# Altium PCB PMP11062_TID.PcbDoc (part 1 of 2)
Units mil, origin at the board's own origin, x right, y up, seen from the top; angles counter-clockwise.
Board outline 8000 x 4750 mil, 2 copper layers (Top Layer, Bottom Layer), stack 62 mil thick; 95 components, 41 nets, 236 pads, 20 vias.
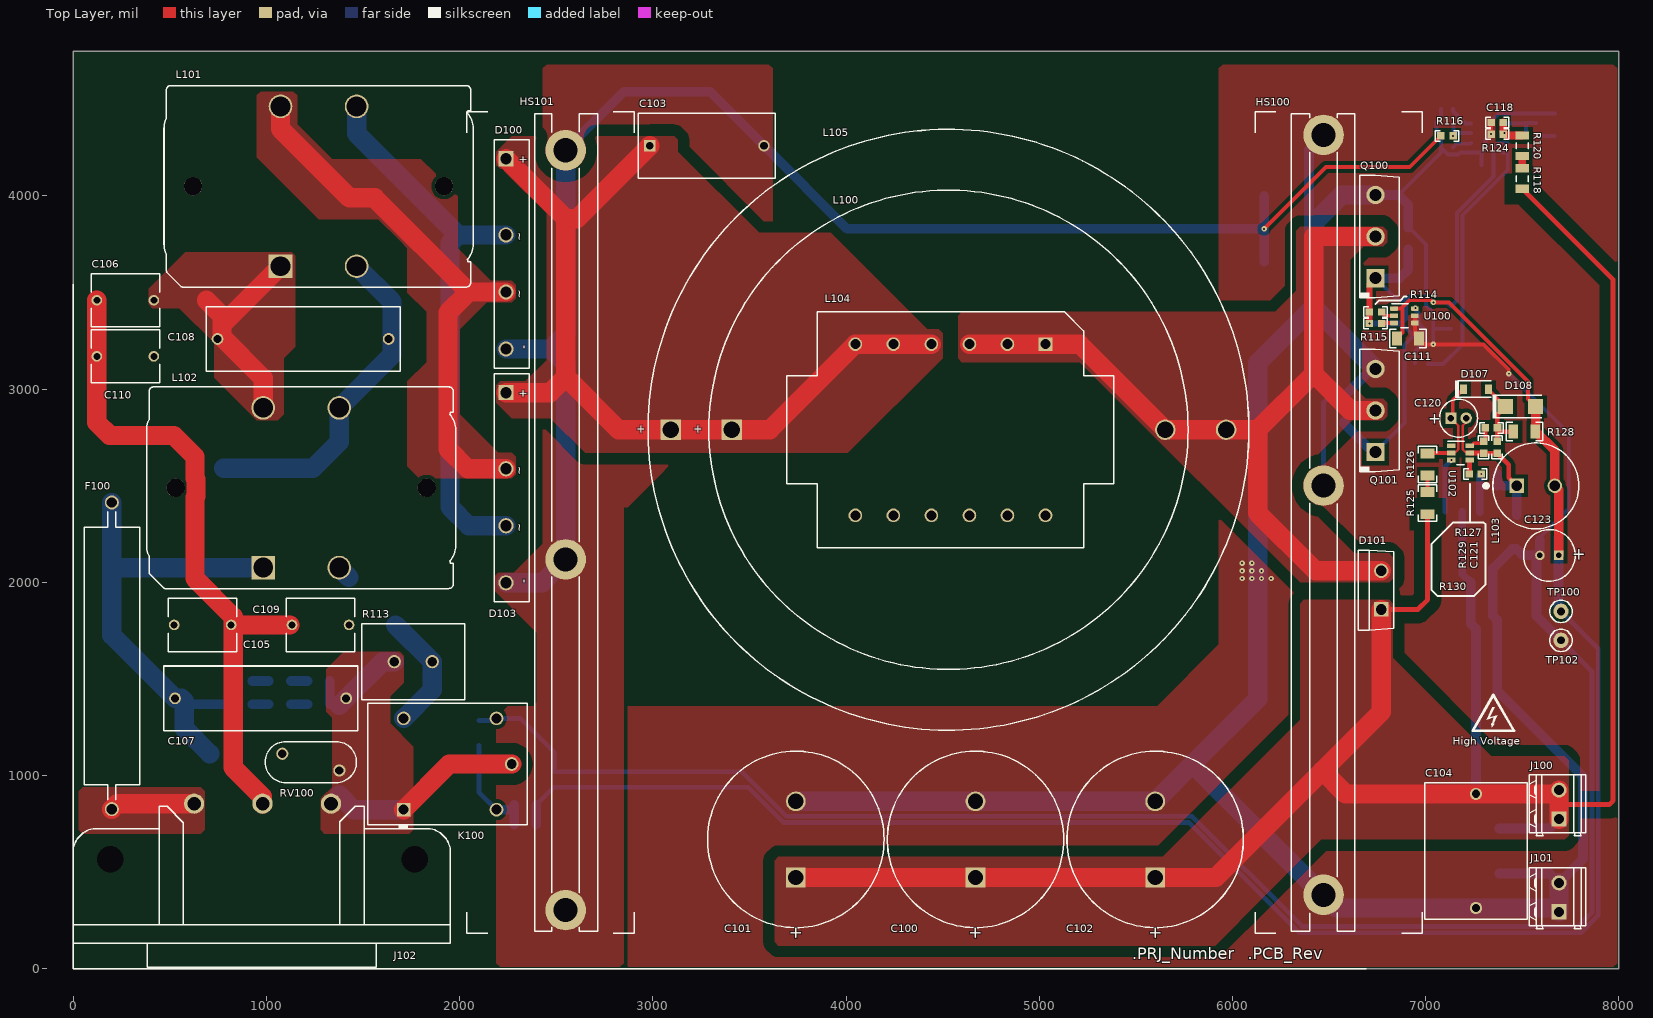
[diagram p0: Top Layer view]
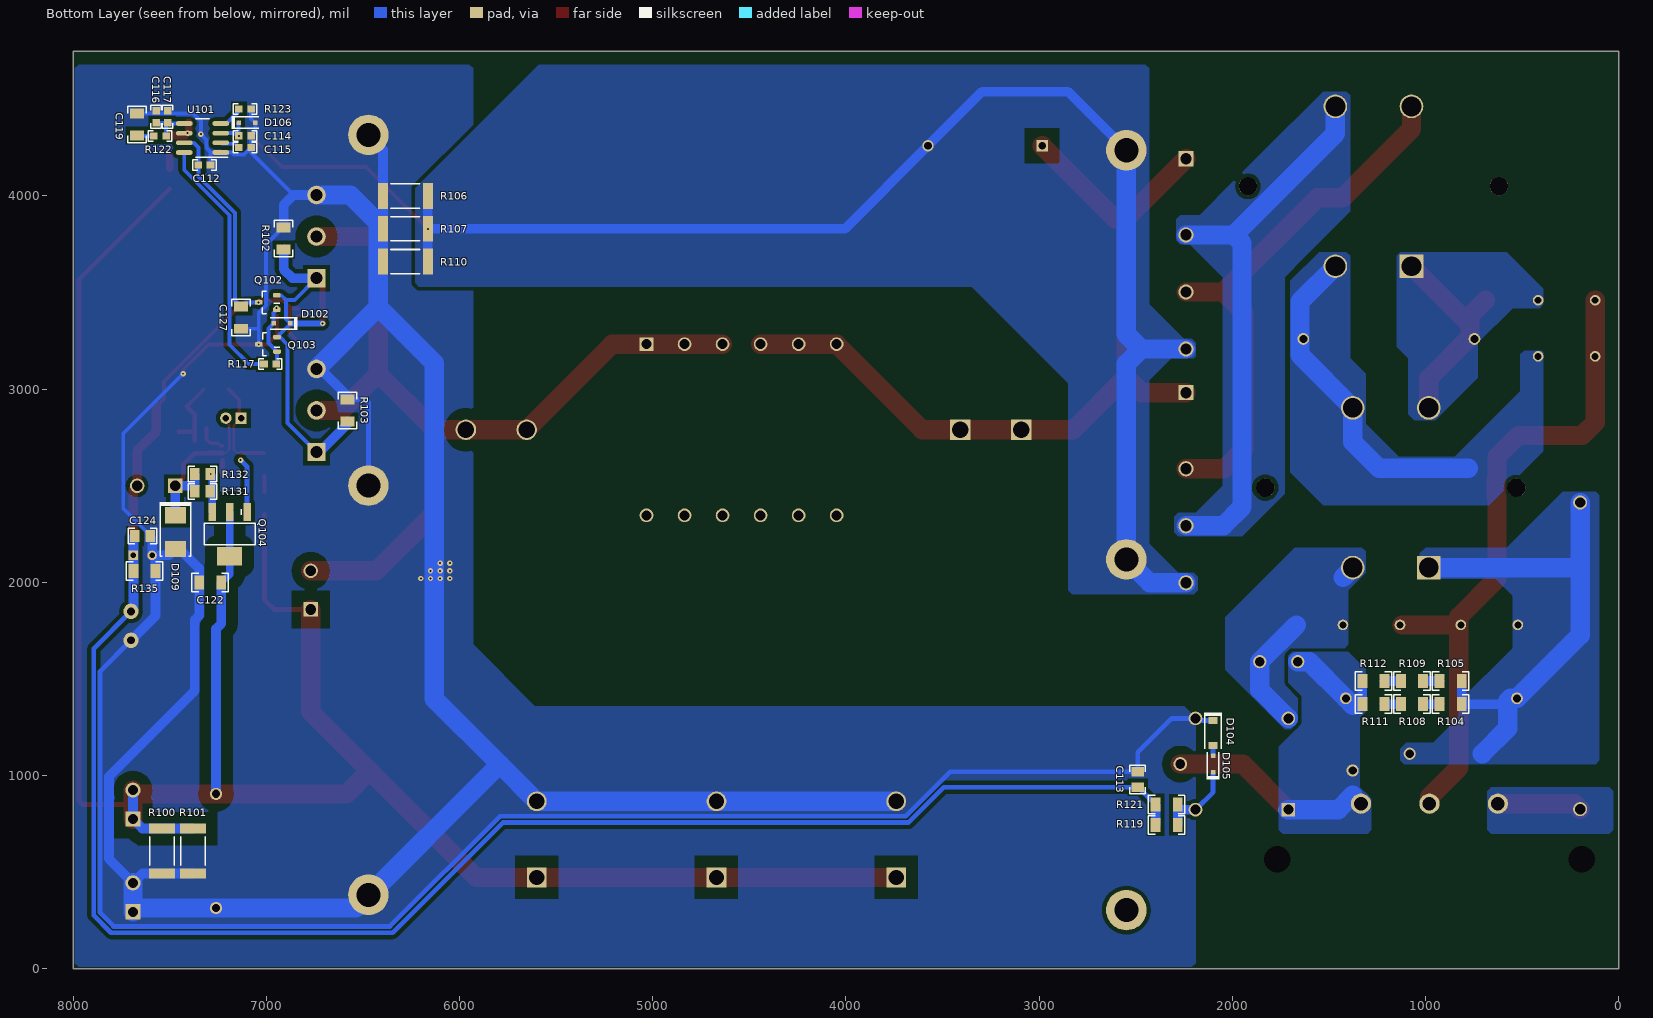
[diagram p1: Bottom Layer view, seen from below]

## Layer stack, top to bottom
Top Solder: solder mask 0.4, Solder Resist, Dk 3.5
Top Layer: signal copper 1.4
Dielectric1: core 59.2, FR-4, Dk 4.8
Bottom Layer: signal copper 1.4
Bottom Solder: solder mask 0.4, Solder Resist, Dk 3.5

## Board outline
0,0 8000,0 8000,4750 0,4750

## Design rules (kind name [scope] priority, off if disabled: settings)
AcuteAngle [All] p1: minimum=4.50000000000000E+0001 checktracksonly=FALSE
AssemblyTestPointUsage [All] p1: valid=2
Clearance Clearance_1 [InNetClass('HV') vs (InNet('GND') OR InNet('NetC103_2'))] p1: gap=60
Clearance Clearance_Keepouts [((IsTrack Or IsArc) And Not InPoly) And IsFree and IsKeepOut vs ((IsTrack Or IsArc) And Not InPoly) And IsFree and IsKeepOut] p2: gap=0
Clearance Clearance_BoardEdge_MountingHoles [OnCopper and InComponentClass('Mounting Holes') vs IsKeepOut] p3: gap=40
Clearance Clearance_BoardEdge_Poly [OnCopper and InPoly vs IsKeepOut] p4: gap=25
Clearance Clearance_BoardEdge [OnCopper and Not InComponentClass('Logo') and not InComponentClass('FiducialMark') and not InRegion(1000,500,4000,800) and Not IsKeepout vs IsKeepOut] p5: gap=75
Clearance Clearance_Poly [InPolygon] p6: gap=20
Clearance [All] p7: gap=7.87
ComponentClearance ComponentClearance_MountingHoles_FiducialMarks [InComponentClass('Mounting Holes') vs InComponentClass('FiducialMark')] p1: gap=20 collisioncheckmode=3 verticalgap=10 showdistances=FALSE
ComponentClearance ComponentClearance_Shunt [InComponentClass('Header') vs InComponentClass('Shunt')] p2: gap=0 collisioncheckmode=3 verticalgap=0 showdistances=FALSE
ComponentClearance ComponentClearance_Logo [InComponentClass('Logo')] p3: gap=5 collisioncheckmode=3 verticalgap=10 showdistances=FALSE
ComponentClearance ComponentClearance_ScrewToNut [(HasFootprint('NY PMS 440 0025 PH')) vs (HasFootprint('Keystone_1902C'))] p4: gap=20 collisioncheckmode=3 verticalgap=100000 showdistances=FALSE
ComponentClearance ComponentClearance_MountingHoles [InComponentClass('Mounting Holes')] p5: gap=20 collisioncheckmode=3 verticalgap=10 showdistances=FALSE
ComponentClearance ComponentClearance_SmallPassives [HasFootprint('0201*') or HasFootprint('0402*') or HasFootprint('0508') or HasFootprint('0603*') or HasFootprint('0612') or HasFootprint('0805*') or HasFootprint('0815*') or HasFootprint('0830*') or HasFootprint('1206*') or HasFootprint('1210*') or HasFootprint('1808*') or HasFootprint('1812*') or HasFootprint('1825*') or HasFootprint('2010*') or HasFootprint('2220*') or HasFootprint('2225*') or HasFootprint('2512*') or HasFootprint('2728*') or HasFootprint('3518*') vs HasFootprint('0201*') or HasFootprint('0402*') or HasFootprint('0508') or HasFootprint('0603*') or HasFootprint('0612') or HasFootprint('0805*') or HasFootprint('0815*') or HasFootprint('0830*') or HasFootprint('1206*') or HasFootprint('1210*') or HasFootprint('1808*') or HasFootprint('1812*') or HasFootprint('1825*') or HasFootprint('2010*') or HasFootprint('2220*') or HasFootprint('2225*') or HasFootprint('2512*') or HasFootprint('2728*') or HasFootprint('3518*')] p6: gap=20 collisioncheckmode=3 verticalgap=20 showdistances=FALSE
ComponentClearance ComponentClearance_THtoSMT [IsThruComponent vs IsSMTComponent] p7: gap=10 collisioncheckmode=3 verticalgap=10 showdistances=FALSE
ComponentClearance ComponentClearance_THtoTH [IsThruComponent vs IsThruComponent] p8: gap=10 collisioncheckmode=3 verticalgap=10 showdistances=FALSE
ComponentClearance [All] p9: gap=10 collisioncheckmode=3 verticalgap=10 showdistances=FALSE
DiffPairsRouting [All] p1: maxlimit=100 minlimit=10 mostfreqgap=10 toplayer_minwidth=15 toplayer_maxwidth=15 toplayer_prefwidth=15 bottomlayer_minwidth=15 bottomlayer_maxwidth=15 bottomlayer_prefwidth=15 maxuncoupledlength=1000
FabricationTestPointUsage TestPointUsage [All] p1: valid=2 allowmultiple=FALSE
FabricationTestpoint Testpoint [All] p1: side=3 testpointundercomponent=TRUE minsize=40 maxsize=100 preferedsize=60 minholesize=0 maxholesize=40 preferedholesize=32 testpointgrid=1 allowsidetop=TRUE allowsidebottom=TRUE usegrid=TRUE gridtolerance=0.01
FanoutControl Fanout_LCC [IsLCC] p1: bgadir=Out bgaviamode=Centered fanoutstyle=Auto fanoutdirection=Alternating viagrid=1 // Fanout_LCC (Default Rule)
FanoutControl Fanout_BGA [IsBGA] p2: bgadir=Out bgaviamode=Centered fanoutstyle=Auto fanoutdirection=Alternating viagrid=1 // Fanout_BGA (Default Rule)
FanoutControl Fanout_Default [All] p4: bgadir=Out bgaviamode=Centered fanoutstyle=Auto fanoutdirection=Alternating viagrid=1 // Fanout_Default (Default Rule)
FanoutControl Fanout_Small [(CompPinCount < 5)] p5: bgadir=Out bgaviamode=Centered fanoutstyle=Auto fanoutdirection=OutThenIn viagrid=1 // Fanout_Small (Default Rule)
Height [All] p1: minheight=0 maxheight=3000 prefheight=500
HoleSize [All] p1: absolutevalues=TRUE maxlimit=251 minlimit=7 maxpercent=80.000 minpercent=20.000
MinimumAnnularRing MinimumAnnularRing_ThermalPadVias [IsVia and InAnyComponent] p1: minimumring=5.91
MinimumAnnularRing [All] p2: minimumring=9
MinimumSolderMaskSliver MinimumSolderMaskSliver_Logo [InComponentClass('Logo') vs InComponentClass('Logo')] p1: minsoldermaskwidth=0.7
MinimumSolderMaskSliver [All] p2: minsoldermaskwidth=2
PlaneConnect [All] p1: planeconnectstyle=Relief reliefexpansion=10 reliefentries=4 reliefconductorwidth=10 reliefairgap=10
PolygonConnect PolygonConnect_7 [All vs IsNamedPolygon('F100_1') Or  IsNamedPolygon('C103_1') Or  IsNamedPolygon('C106_1') Or  IsNamedPolygon('D100_2') Or  IsNamedPolygon('C106_1') Or  IsNamedPolygon('C105_1') Or  IsNamedPolygon('C109_2') Or  IsNamedPolygon('B+') Or  IsNamedPolygon('C107_2') Or  IsNamedPolygon('C108_2') Or  IsNamedPolygon('F100_1') Or  IsNamedPolygon('C103_2') Or  IsNamedPolygon('C107_2') Or  IsNamedPolygon('D100_3') Or  IsNamedPolygon('D101_2')] p1: connectstyle=Direct reliefconductorwidth=10 reliefentries=4 polygonreliefangle="90 Angle" airgapwidth=10
PolygonConnect PolygonConnect_6 [All vs IsNamedPolygon('GND2') Or  IsNamedPolygon('SGND') Or  IsNamedPolygon('GND1') Or  IsNamedPolygon('C901_1') Or  IsNamedPolygon('SGND') Or  IsNamedPolygon('GND2') Or  IsNamedPolygon('GND1')] p2: connectstyle=Direct reliefconductorwidth=10 reliefentries=4 polygonreliefangle="90 Angle" airgapwidth=10
PolygonConnect PolygonConnect_5 [All vs IsNamedPolygon('GND1') Or  IsNamedPolygon('GND1')] p3: connectstyle=Direct reliefconductorwidth=10 reliefentries=4 polygonreliefangle="90 Angle" airgapwidth=10
PolygonConnect PolygonConnect_4 [All vs IsNamedPolygon('C21_1') Or  IsNamedPolygon('C5_1') Or  IsNamedPolygon('C12_2') Or  IsNamedPolygon('C2_2') Or  IsNamedPolygon('C13_1') Or  IsNamedPolygon('C28_1') Or  IsNamedPolygon('C6_1') Or  IsNamedPolygon('GND') Or  IsNamedPolygon('GND2') Or  IsNamedPolygon('C14_1') Or  IsNamedPolygon('C13_1') Or  IsNamedPolygon('Q1_3') Or  IsNamedPolygon('C14_1') Or  IsNamedPolygon('C5_1') Or  IsNamedPolygon('GND2') Or  IsNamedPolygon('C28_1') Or  IsNamedPolygon('D5_2') Or  IsNamedPolygon('D6_2') Or  IsNamedPolygon('D2_1') Or  IsNamedPolygon('C12_2') Or  IsNamedPolygon('D2_1') Or  IsNamedPolygon('C4_1') Or  IsNamedPolygon('C4_1') Or  IsNamedPolygon('C2_2') Or  IsNamedPolygon('GND') Or  IsNamedPolygon('C33_1') Or  IsNamedPolygon('C9_1')] p4: connectstyle=Direct reliefconductorwidth=10 reliefentries=4 polygonreliefangle="90 Angle" airgapwidth=10
PolygonConnect PolygonConnect_3 [All vs IsNamedPolygon('C28_1') Or  IsNamedPolygon('C12_2') Or  IsNamedPolygon('C28_1') Or  IsNamedPolygon('C9_1') Or  IsNamedPolygon('D5_2') Or  IsNamedPolygon('C12_2') Or  IsNamedPolygon('C2_2') Or  IsNamedPolygon('C14_1') Or  IsNamedPolygon('C4_1') Or  IsNamedPolygon('C14_1') Or  IsNamedPolygon('D6_2') Or  IsNamedPolygon('GND2') Or  IsNamedPolygon('Q1_3') Or  IsNamedPolygon('C5_1') Or  IsNamedPolygon('D2_1') Or  IsNamedPolygon('C4_1') Or  IsNamedPolygon('C13_1') Or  IsNamedPolygon('C5_1') Or  IsNamedPolygon('C13_1') Or  IsNamedPolygon('C33_1') Or  IsNamedPolygon('D2_1') Or  IsNamedPolygon('GND') Or  IsNamedPolygon('GND') Or  IsNamedPolygon('GND2') Or  IsNamedPolygon('C2_2') Or  IsNamedPolygon('C6_1') Or  IsNamedPolygon('C21_1')] p5: connectstyle=Direct reliefconductorwidth=10 reliefentries=4 polygonreliefangle="90 Angle" airgapwidth=10
PolygonConnect PolygonConnect_2 [All vs IsNamedPolygon('C21_1') Or  IsNamedPolygon('C4_1') Or  IsNamedPolygon('D5_2') Or  IsNamedPolygon('C5_1') Or  IsNamedPolygon('C14_1') Or  IsNamedPolygon('C13_1') Or  IsNamedPolygon('C4_1') Or  IsNamedPolygon('C33_1') Or  IsNamedPolygon('C12_2') Or  IsNamedPolygon('D2_1') Or  IsNamedPolygon('C2_2') Or  IsNamedPolygon('C28_1') Or  IsNamedPolygon('C12_2') Or  IsNamedPolygon('D2_1') Or  IsNamedPolygon('C5_1') Or  IsNamedPolygon('Q1_3') Or  IsNamedPolygon('GND') Or  IsNamedPolygon('D6_2') Or  IsNamedPolygon('C6_1') Or  IsNamedPolygon('C2_2') Or  IsNamedPolygon('C14_1') Or  IsNamedPolygon('C28_1') Or  IsNamedPolygon('C13_1') Or  IsNamedPolygon('C9_1') Or  IsNamedPolygon('GND')] p6: connectstyle=Direct reliefconductorwidth=10 reliefentries=4 polygonreliefangle="90 Angle" airgapwidth=10
PolygonConnect PolygonConnect_1 [All vs IsNamedPolygon('C28_1') Or  IsNamedPolygon('D5_2') Or  IsNamedPolygon('C5_1') Or  IsNamedPolygon('C5_1') Or  IsNamedPolygon('D2_1') Or  IsNamedPolygon('C21_1') Or  IsNamedPolygon('C9_1') Or  IsNamedPolygon('C4_1') Or  IsNamedPolygon('C14_1') Or  IsNamedPolygon('C28_1') Or  IsNamedPolygon('C6_1') Or  IsNamedPolygon('C12_2') Or  IsNamedPolygon('C33_1') Or  IsNamedPolygon('C4_1') Or  IsNamedPolygon('C13_1') Or  IsNamedPolygon('C12_2') Or  IsNamedPolygon('D6_2') Or  IsNamedPolygon('C2_2') Or  IsNamedPolygon('C14_1') Or  IsNamedPolygon('D2_1') Or  IsNamedPolygon('C2_2') Or  IsNamedPolygon('C13_1')] p7: connectstyle=Direct reliefconductorwidth=10 reliefentries=4 polygonreliefangle="90 Angle" airgapwidth=10
PolygonConnect [All] p8: connectstyle=Relief reliefconductorwidth=10 reliefentries=4 polygonreliefangle="90 Angle" airgapwidth=10
RoutingVias ThermalPadVias [IsVia and InAnyComponent] p1: holewidth=7.87 width=19.68 viastyle="Through Hole" minholewidth=7.87 minwidth=19.68 maxholewidth=12.99 maxwidth=23.62
RoutingVias [All] p2: holewidth=16 width=34 viastyle="Through Hole" minholewidth=7.87 minwidth=26 maxholewidth=40 maxwidth=65
SilkToBoardRegionClearance [Not ((IsComment or IsDesignator) And (Hide <> 'False')) and not InRegion(1000,500,4000,800)] p1:
SilkToSilkClearance SilkToSilkClearance_Pb-FreeLogo [(HasFootprint('Pb-Free_Overlay_Medium') OR HasFootprint('Pb-Free_Overlay_Small')) vs (HasFootprint('Pb-Free_Overlay_Medium') OR HasFootprint('Pb-Free_Overlay_Small'))] p1: silktosilkclearance=0
SilkToSilkClearance [All] p2: silktosilkclearance=1
SilkToSolderMaskClearance "Silk to Solder Mask Opening" [All] p1: minsilkscreentomaskgap=1 clearancetoexposedcopper=FALSE
SolderMaskExpansion [All] p1: expansion=1.97
UnpouredPolygon [All] p1: allowunpoured=FALSE
Width [All] p1: maxlimit=100 minlimit=6 preferedwidth=10 checkconnectedcopper=TRUE
13 further rules are at their usual default settings.

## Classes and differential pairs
net class HV: B+ NetC103_1 NetC105_1 NetC106_1 NetC107_2 NetC109_2 NetD101_2 NetF100_1

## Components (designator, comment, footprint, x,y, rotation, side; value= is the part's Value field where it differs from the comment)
C100 "450HXG180MEFCSN22X45" SMQ_2200X2500 4670,670 r90 top
C101 "450HXG180MEFCSN22X45" SMQ_2200X2500 3740,670 r90 top
C102 "450HXG180MEFCSN22X45" SMQ_2200X2500 5600,670 r90 top
C103 "B32922C3334M" B32922_14.5mm 3280,4260 r0 top
C104 "450MPK105J" MPK_1800x2000x1350 7260,610 r270 top
C105 "DE6E3KJ222MN3A" E_900x700x900 670,1780 r0 top
C106 "DE6E3KJ222MN3A" E_900x700x900 270,3460 r180 top
C107 "ECQ-U2A474ML" CAPRR2250W80L2550T850H1750 970,1400 r0 top
C108 "ECQ-U2A474ML" CAPRR2250W80L2550T850H1750 1190,3260 r0 top
C109 "DE6E3KJ222MN3A" E_900x700x900 1280,1780 r0 top
C110 "DE6E3KJ222MN3A" E_900x700x900 270,3170 r0 top
C111 "C3216X7R1H105K160AB" 1206 6907.68,3262.49 r0 top
C112 "C0603C474K8RACTU" 0603 7320,4160 r180 bottom
C113 "0805YD105KAT2A" 0805_HV 2490,980 r270 bottom
C114 "06031C471JAT2A" 0603 7110,4311.46 r180 bottom
C115 "C0603C102J5RACTU" 0603 7110,4251.46 r180 bottom
C116 "C0603C105K4PACTU" 0603 7570,4410 r90 bottom
C117 "C0603C474K8RACTU" 0603 7510,4410 r90 bottom
C118 "CL10C102JB8NNNC" 0603 7370,4380 r180 top
C119 "GRM31MR61A106KE19L" 1206 7670,4370 r90 bottom
C120 "UVR1V100MDD1TA" CAPPR2-5x11 7170,2850 r0 top
C121 "06035A220JAT2A" 0603 7370,2700 r270 top
C122 "GRM31BR72J682KW01L" 1206 7290,2000 r0 bottom
C123 "EEU-FR1E151B" CAPPR250W50D630H1120 7640,2140 r180 top
C124 "08055C105KAT2A" 0805_HV 7640,2240 r180 bottom
C127 "C3216X7R1H105K160AB" 1206 7130,3370 r270 bottom
D100 "D25XB60-7000" 5S 2240,3700 r270 top
D101 "CVFD20065A" TO-220-2 6770,1960 r90 top
D102 "BAT54HT1G" sod-323 6918.7,3340.16 r0 bottom
D103 "D25XB60-7000" 5S 2240,2490 r270 top
D104 "MMSZ4699T1G" SOD-123 2100,1220 r270 bottom
D105 "BAS316,115" sod-323 2100,1060 r90 bottom
D106 "BAT54HT1G" sod-323 7100,4380 r180 bottom
D107 "1N4148W-7-F" SOD-123 7260,3000 r0 top
D108 "ES1J-TP" SMA 7490,2910 r0 top
D109 "MURS160-13-F" SMB 7470,2260 r270 bottom
F100 "0325020.MXP" FUSE_0325 200,1620 r90 top
"High Voltage" "DANGER HIGH VOLTAGE" IEC_HighVoltage_Small 7350,1320 r0 top
HS100 "782653B04250G" HEATSINK_782653B04250G 6550,2310 r270 top
HS101 "782653B04250G" HEATSINK_782653B04250G 2470,2310 r90 top
J100 "691214310002" Wurth_691214310002 7690,850 r90 top
J101 "691214310002" Wurth_691214310002 7690,370 r90 top
J102 "703W-00/54" CONN_QUALTEK-703W-0054 980,460 r180 top
K100 "875B-1CC-F-S-12VDC" RELAY_875 1990,1060 r90 top
L100 "G154015" G154015 4530,2790 r0 top
L101 "7448062105" WE-CMBNC_XXL 1270,4050 r90 top
L102 "7448062105" WE-CMBNC_XXL 1180,2490 r90 top
L103 "RFS1113-224ME" RFS1113 7570,2500 r0 top
L104 "G154021LF" G154021LF 4540,2790 r270 top
L105 "G154016" G154016 4530,2790 r0 top
Q100 "IPW60R099CP" TO-247 6740,3790 r90 top
Q101 "IPW60R099CP" TO-247 6740,2890 r90 top
Q102 "FMMT620TA" SOT-23 6992.13,3449.06 r0 bottom
Q103 "FMMT718TA" SOT-23 6991.66,3232.17 r0 bottom
Q104 "STN2580" SOT-223 7190,2250 r270 bottom
R100 "CRCW2512330KJNEG" 2512 7539.68,610 r90 bottom
R101 "CRCW2512330KJNEG" 2512 7380,610 r90 bottom
R102 "CRCW120620K0JNEA" 1206 6910,3780 r270 bottom
R103 "CRCW120620K0JNEA" 1206 6580,2890 r270 bottom
R104 "CRCW1206432KFKEA" 1206 870,1370 r180 bottom
R105 "CRCW1206432KFKEA" 1206 870,1490 r180 bottom
R106 "1-2176057-4" 2512 6280,4000 r0 bottom
R107 "1-2176057-4" 2512 6280,3830 r0 bottom
R108 "CRCW1206432KFKEA" 1206 1070,1370 r180 bottom
R109 "CRCW1206432KFKEA" 1206 1070,1490 r180 bottom
R110 "1-2176057-4" 2512 6280,3660 r0 bottom
R111 "CRCW1206432KFKEA" 1206 1270,1370 r180 bottom
R112 "CRCW1206432KFKEA" 1206 1270,1490 r180 bottom
R113 "TWW10J10RE" TWW10 1760,1590 r180 top
R114 "CRCW060310R0JNEAHP" 0603 6740,3400 r0 top
R115 "CRCW06031R00JNEA" 0603 6740,3340 r180 top
R116 "CRCW0603221RFKEA" 0603 7110,4311.46 r180 top
R117 "CRCW060310R0JNEAHP" 0603 6980,3130 r0 bottom
R118 "CRCW1206499KFKEA" 1206L 7500,4090 r270 top
R119 "CRCW1206150RJNEA" 1206 2340,745.04 r0 bottom
R120 "CRCW1206499KFKEA" 1206L 7500,4260 r270 top
R121 "CRCW1206150RJNEA" 1206 2340,850 r0 bottom
R122 "CRCW06035K90FKEA" 0603 7550,4310 r180 bottom
R123 "CRCW060310K5FKEA" 0603 7110,4450 r0 bottom
R124 "CRCW060313K3FKEA" 0603 7370,4320 r0 top
R125 "CRCW12063M30JNEA" 1206 7010,2410 r90 top
R126 "CRCW12063M30JNEA" 1206 7010,2610 r90 top
R127 "CRCW060349K9FKEA" 0603 7340,2800 r0 top
R128 "CRCW1206475KFKEA" 1206 7510,2780 r180 top
R129 "CRCW060317K8FKEA" 0603 7300,2700 r90 top
R130 "CRCW0603511RFKEA" 0603 7256,2561.46 r180 top
R131 "CRCW08051R20JNEA" 0805_HV 7330,2471.46 r0 bottom
R132 "CRCW08051R20JNEA" 0805_HV 7330,2561.46 r0 bottom
R135 "CRCW120612K0JNEA" 1206 7630,2060 r0 bottom
RV100 "S10K275E2" VAR_S10K275E2 1230,1070 r180 top
TP100 "5000" Keystone5000 7700,1850 r90 top
TP102 "5001" Keystone5001 7700,1700 r90 top
U100 "UCC27511DBVR" DBV0006A_N#1 6890,3380 r0 top
U101 "UCC28180D" D0008A_N 7330,4300 r0 bottom
U102 "UCC28722DBV" DBV0006A_N#2 7180,2670 r0 top

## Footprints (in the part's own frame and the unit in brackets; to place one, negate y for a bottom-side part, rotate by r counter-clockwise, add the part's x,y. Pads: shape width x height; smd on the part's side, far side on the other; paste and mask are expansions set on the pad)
5S [mm] "TH, 4-Leads, Body 4.6x30mm"
  rect 2x2 hole 1.5: 1(-12.5,0)
  round 2 hole 1.5: 2(-2.5,0) 3(5,0) 4(12.5,0)
  silkscreen extent -15,-1.55 15,3.05, body extent -15,-1.55 15,3.05, height 24
0603 [mm] "0603 from SM-752 data"
  rect 1x0.95 smd: 1(-0.8,0) 2(0.8,0)
  silkscreen extent -1.52,-0.69 1.52,0.69, body extent -0.87,-0.47 0.87,0.47, height 1
0805_HV [mil] "0805 with 30mil clearance between pads"
  rect 50x63 smd: 1(-40,0) 2(40,0)
  silkscreen extent -74,-40 74,40, body extent -43,-29 43,29, height 43
1206 [mm] "1206 from SM-752 data"
  rect 1.3x1.85 smd: 1(-1.45,0) 2(1.45,0)
  silkscreen extent -2.4,-1.21 2.4,1.21, body extent -1.7,-0.9 1.7,0.9, height 1.35
1206L [mm] "1206 from SM-752 data"
  rect 1.1x1.75 smd: 1(-1.35,0) 2(1.35,0)
  silkscreen extent -0.4,-0.77 0.4,0.77, body extent -1.7,-0.9 1.7,0.9, height 1.35
2512 [mm] "Chip Resistor, Body 6.3x3.2mm, IPC Medium Density"
  rect 1.3x3.4 smd: 1(-2.95,0) 2(2.95,0)
  silkscreen extent -1.9,-1.6 1.9,1.6, body extent -3.22,-1.67 3.22,1.67, height 0.71
B32922_14.5mm [mm] "Epcos film capacitors, 15mm spacing"
  rect 1.5x1.5 hole 1: 1(-7.5,0)
  round 1.5 hole 1: 2(7.5,0)
  silkscreen extent -9,-4.25 9,4.25, body extent -9,-4.25 9,4.25, height 14.5
CAPPR2-5x11 [mm] "Capacitor, Electrolytic, Radial; Body 5 x 11 mm (Dia.xH typ); Pin Spacing 2 mm (typ)"
  rect 1.5x1.5 hole 0.85: 1(-1,0)
  round 1.5 hole 0.85: 2(1,0)
  silkscreen extent -2.5,-2.5 2.5,2.5, body extent -2.53,-2.53 2.53,2.52, height 11.29
CAPPR250W50D630H1120 [mm] "PANASONIC"
  rect 1.25x1.25 hole 0.75: 1(-1.25,0)
  round 1.25 hole 0.75: 2(1.25,0)
  silkscreen extent -3.4,-3.4 3.4,3.4, body extent -3.37,-3.39 3.4,3.39, height 12.21
CAPRR2250W80L2550T850H1750 [mm] "PANASONIC"
  round 1.55 hole 1.05: 1(-11.25,0) 2(11.25,0)
  silkscreen extent -12.75,-4.25 12.75,4.25, body extent -12.75,-4.25 12.75,4.25, height 17.5
CONN_QUALTEK-703W-0054 [mil] "AC Receptacle"
  round 105 hole 70: 1(354.33,-395) 2(-354.33,-395) 3(0,-395)
  round 39.37 hole 137.8 unplated: MH1(-787.4,-107.36) MH2(787.4,-107.36)
  silkscreen extent -972,-380 981,452, body extent -972,-477 981,452, height 1130
D0008A_N [mm] "SOIC, 8-Leads, Body 4.9x3.9mm, Pitch 1.27mm, IPC Medium Density"
  oval 2.2x0.6 smd: 1(-2.4,1.905) 2(-2.4,0.635) 3(-2.4,-0.635) 4(-2.4,-1.905) 5(2.4,-1.905) 6(2.4,-0.635) 7(2.4,0.635) 8(2.4,1.905)
  silkscreen extent -3.3,-2.5 0.9,2.5, body extent -3,-2.45 3,2.45, height 1.63
DBV0006A_N#1 [mm] "SOT23, 6-Leads, Body 2.9x1.6mm, Pitch 0.95mm, Lead Span 2.8mm, IPC Medium Density"
  rrect17% 1x0.6 smd: 1(-1.375,0.95) 2(-1.375,0) 3(-1.375,-0.95) 4(1.375,-0.95) 5(1.375,0) 6(1.375,0.95)
  silkscreen extent -1.68,-1.55 0.5,1.55, body extent -1.42,-1.46 1.42,1.46, height 1.12
DBV0006A_N#2 [mm] "SOT23, 6-Leads, Body 2.9x1.6mm, Pitch 0.95mm, Lead Span 2.8mm, IPC Medium Density"
  rect 1.1x0.65 smd: 1(-1.2,0.95) 2(-1.2,0) 3(-1.2,-0.95) 4(1.2,-0.95) 5(1.2,0) 6(1.2,0.95)
  silkscreen extent -1.68,-1.55 0.5,1.55, body extent -1.42,-1.46 1.42,1.46, height 1.11
E_900x700x900 [mm] "TH, 2- Leads, Body 9x7mm, Pin Spacing 7.5mm"
  round 1.4 hole 0.9: 1(-3.75,0) 2(3.75,0)
  silkscreen extent -4.5,-3.5 4.5,3.5, body extent -4.49,-3.5 4.49,3.5, height 11.96
FUSE_0325 [mm] "TH, 2-Leads, Dia 6.985mm, Pin Spacing 40.32mm"
  round 1.85 hole 1.35: 1(-20.16,0) 2(20.16,0)
  silkscreen extent -18.95,-3.64 18.95,3.64, body extent -20.7,-3.64 20.7,3.64, height 7.26
G154015 [mm] "TH, 2-Leads, Dia 63mm, Pin Spacing 57mm"
  rect 2.7x2.7 hole 2.2: 1(-28.5,0)
  round 2.7 hole 2.2: 2(28.5,0)
  silkscreen extent -31.5,-31.5 31.5,31.5, body extent -31.51,-31.51 31.51,31.51, height 35
G154016 [mm] "TH, 2-Leads, Dia 79mm, Pin Spacing 73mm"
  rect 2.7x2.7 hole 2.2: 1(-36.5,0)
  round 2.7 hole 2.2: 2(36.5,0)
  silkscreen extent -39.5,-39.5 39.5,39.5, body extent -39.51,-39.51 39.51,39.51, height 43
G154021LF [mm] "TH, 12-Leads, Body 43x31mm, Pitch 5mm"
  rect 1.8x1.8 hole 1.3: 1(-11.25,12.5)
  round 1.8 hole 1.3: 2(-11.25,7.5) 3(-11.25,2.5) 4(-11.25,-2.5) 5(-11.25,-7.5) 6(-11.25,-12.5) 7(11.25,-12.5) 8(11.25,-7.5) 9(11.25,-2.5) 10(11.25,2.5) 11(11.25,7.5) 12(11.25,12.5)
  silkscreen extent -15.5,-21.5 15.5,21.5, body extent -15.5,-21.5 15.5,21.5, height 49
HEATSINK_782653B04250G [mil] "Aavid"
  round 210 hole 125: 1(-2006.1,-78.66) 2(-191.14,-78.66) 3(1926.97,-78.66)
  silkscreen extent -2125,-433 2125,433, body extent -2125,-430 2120,420, height 1122
IEC_HighVoltage_Small [mil]
  silkscreen extent -107,-88 107,97
Keystone5000 [mil] "For Keystone 500x miniature loop terminals"
  round 80 hole 40: 1(0,0)
  silkscreen extent -58,-58 58,58, body extent -49,-49 49,49, height 182
Keystone5001 [mil] "For Keystone 500x miniature loop terminals"
  round 80 hole 40: 1(0,0)
  silkscreen extent -58,-58 58,58, body extent -49,-49 49,49, height 182
MPK_1800x2000x1350 [mm] "Rubycon"
  round 1.6 hole 1.1: 1(-7.5,0) 2(7.5,0)
  silkscreen extent -9,-6.75 9,6.75, body extent -9,-6.75 9,6.75, height 20
RELAY_875 [mm] "TH, 5-Leads, Body 21x16mm"
  rect 1.8x1.8 hole 1.3: 1(-6,7.1)
  round 1.8 hole 1.3: 2(6,7.1) 3(0,-7.1) 4(-6,-5.1) 5(6,-5.1)
  silkscreen extent -8.5,-9.15 8,11.85, body extent -8,-9.15 8,11.85, height 20.6
RFS1113 [mm] "TH, 2-Leads, Dia 11mm, Pin Spacing 5mm"
  rect 1.9x1.9 hole 1.37: 1(-2.5,0)
  round 1.9 hole 1.37: 2(2.5,0)
  silkscreen extent -6.8,-5.65 5.65,5.65, body extent -7.78,-7.78 7.78,7.78, height 12.5
SMA [mm] "Molded Diode, 2-Leads, Body 4.3x2.6mm, IPC Medium Density, based on OnSemi component dimensions and land pattern"
  rect 2x2 smd: 1(-2,0) 2(2,0)
  silkscreen extent -3.66,-1.57 2.79,1.57, body extent -2.6,-1.3 2.6,1.3, height 2.42
SMB [mil] "Molded Diode, 2-Leads, Body 5.4x3.6mm, IPC Medium Density, based on OnSemi component dimensions"
  rect 85x107.99 smd: 1(-87.01,0) 2(87.01,0)
  silkscreen extent -155,-82 125,82, body extent -106,-71 106,71, height 91
SMQ_2200X2500 [mm] "United Chemi-Con Inc"
  rect 2.6x2.6 hole 2: 1(-5,0)
  round 2.6 hole 2: 2(5,0)
  silkscreen extent -11.6,-11.6 11.6,11.6, body extent -11.41,-11.48 11.47,11.48, height 27.01
SOD-123 [mm] "On Semi recommended land pattern"
  rect 0.915x1.22 smd: 1(-1.637,0) 2(1.637,0)
  silkscreen extent -2.74,-1.17 2.03,1.17, body extent -1.93,-0.9 1.93,0.9, height 1.35
sod-323 [mm] "NXP recommended land pattern"
  rect 0.6x0.6 smd paste-0.05: 1(-1.1,0) 2(1.1,0)
  silkscreen extent -2.06,-0.86 1.53,0.86, body extent -1.3,-0.67 1.3,0.68, height 1.1
SOT-23 [mm] "SOT23, 3-Leads, Body 2.9x1.3mm, Pitch 0.95mm, Lead Span 2.5mm, IPC Medium Density"
  rrect50% 1x0.6 smd: 1(-1.2,0.95) 2(-1.2,-0.95) 3(1.2,0)
  silkscreen extent -1.58,-1.5 0.7,1.5, body extent -1.16,-1.45 1.21,1.45, height 1
SOT-223 [mm] "SOT223/SC73, 4-Leads, Body 6.5x3.5mm, Pitch 2.3mm, Lead Span 7mm, IPC Medium Density"
  rrect10% 2.4x1 smd: 1(-2.9,2.3) 2(-2.9,0) 3(-2.9,-2.3)
  rrect4% 2.4x3.3 smd: 4(2.9,0)
  silkscreen extent -3.33,-3.35 1.4,3.35, body extent -3.5,-3.25 3.5,3.25, height 1.62
TO-220-2 [mm] "CREE"
  rect 1.9x1.9 hole 1.4: 1(-2.54,0)
  round 1.9 hole 1.4: 2(2.54,0)
  silkscreen extent -5.25,-1.64 5.26,3.01, body extent -5.21,-1.57 5.21,3.12, height 19.47
TO-247 [mil] "Standard TO-247"
  rect 95x95 hole 62: 1(-215,0)
  round 95 / inner round 74.8 / far side round 96 hole 62: 2(0,0) 3(215,0)
  silkscreen extent -318,-124 318,81, body extent -318,-124 318,81, height 1007
TWW10 [mm] "TH, 2-Leads, Body 13.5x10mm, Pin Spacing 5mm"
  round 1.75 hole 1.25: 1(-2.5,0) 2(2.5,0)
  silkscreen extent -6.75,-5 6.75,5, body extent -6.7,-5 6.81,5, height 50
VAR_S10K275E2 [mm] "EPCOS"
  round 1.6 hole 1.1: 1(-3.75,1.1) 2(3.75,-1.1)
  silkscreen extent -6,-2.7 6,2.7, body extent -5.98,-2.7 5.98,2.7, height 14.99
WE-CMBNC_XXL [mm] "TH, 4-Leads, Body 48x27mm"
  rect 3.1x3.1 hole 2.6: 1(-10.5,5)
  round 3.1 hole 2.6: 2(-10.5,-5) 3(10.5,-5) 4(10.5,5)
  round 2.4 hole 2.4 unplated mask+0: MH1(0,16.5) MH2(0,-16.5)
  silkscreen extent -13.25,-20.32 13.25,20.32, body extent -13.25,-20.32 13.25,20.32, height 39.1
Wurth_691214310002 [mm] "WE"
  rect 2x2 hole 1.3: 1(-1.905,0)
  round 2 hole 1.3: 2(1.905,0)
  silkscreen extent -4.12,-3.5 3.9,3.9, body extent -4.12,-3.5 3.9,3.9, height 8.52

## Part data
C100 C101 C102: library part ESMQ451VSN101MP25S, "CAP ALUM 180UF 450V 20% SNAP"
C103: "CAP, Film, 0.33uF, 630V, +/-20%, TH"
C104: library part 450MPK225J, "CAP FILM 1UF 450VDC RADIAL"
C105 C106 C109 C110: "CAP, CERM, 2200 pF, 300 V, +/- 20%, E, TH, 2- Leads, Body 9x7mm, Pin Spacing 7.5mm"
C107 C108: "CAP, Film, 0.47 µF, 275 V, +/- 20%, TH"
C111 C127: "CAP, CERM, 1 µF, 50 V, +/- 10%, X7R, 1206"
C112 C117: "CAP, CERM, 0.47 µF, 10 V, +/- 10%, X7R, 0603"
C113: "CAP, CERM, 1uF, 16V, +/-10%, X5R, 0805"
C114: "CAP, CERM, 470 pF, 100 V, +/- 5%, X7R, 0603"
C115 C118: "CAP, CERM, 1000 pF, 50 V, +/- 5%, X7R, 0603"
C116: "CAP, CERM, 1 µF, 16 V, +/- 10%, X5R, 0603"
C119: "CAP, CERM, 10 µF, 10 V, +/- 10%, X5R, 1206"
C120: "CAP, AL, 10uF, 35V, +/-20%, TH"
C121: "CAP, CERM, 22pF, 50V, +/-5%, C0G/NP0, 0603"
C122: "CAP, CERM, 6800 pF, 630 V, +/- 10%, X7R, 1206"
C123: library part EEU-EB1E101S, "CAP ALUM 150UF 25V 20% RADIAL"
C124: "CAP, CERM, 1uF, 50V, +/-10%, X7R, 0805"
D100 D103: "Diode, Switching-Bridge, 600 V, 3.5 A, TH"
D101: library part C3D08060A, "DIODE SCHKY SIC 650V 20A TO-220"
D102 D106: "Diode, Schottky, 30 V, 0.2 A, SOD-323"
D104: "Diode, Zener, 12 V, 500 mW, SOD-123"
D105: "Diode, Ultrafast, 100 V, 0.25 A, SOD-323"
D107: "Diode, Ultrafast, 100V, 0.15A, SOD-123"
D108: library part ES1D-13-F, "DIODE FAST REC 600V 1A DO214AC"
D109: "Diode, Ultrafast, 600V, 1A, SMB"
F100: "Fuse, 20 A, 60 V, TH"
"High Voltage": library part IEC_HighVoltage, "IEC 61010-1 High Voltage Warning"
HS100 HS101: "HEATSINK VERT MAX CLIP, BLACK, 4.25 INCHES"
J100 J101: "Terminal Block, 2x1, 3.81mm, 24-16 AWG, 10A, 300VAC, TH"
J102: "AC Receptacle, 10A 250VAC"
K100: "Relay, SPDT ( 1 Form C), 16A, 12 VDC, TH"
L100: "Inductor, Toroid, Ferrite, 570uH, 13 A, 0.03 ohm, TH"
L101 L102: "Coupled inductor, 5 mH,  A, 0.0065 ohm, +/- 50%, TH"
L103: library part RFS1113-104ME, "Inductor, Shielded, Ferrite, 220 µH, 1 A, 0.281 ohm, TH"
L104: "Inductor, 300 µH, 7 A, 0.194 ohm, TH"
L105: "Inductor, Toroid, Ferrite, 2.54mH, 13 A, 0.091 ohm, TH"
Q100 Q101: library part IPW60R045CP, "MOSFET N-CH 650V 31A TO-247"
Q102: library part "FMMT497, Zetex", "TRANS NPN 80V 1.5A SOT23-3"
Q103: library part "FMMT718TA, Diodes Inc.", "Transistor, PNP, 20 V, 1.5 A, SOT-23"
Q104: library part "DZTA42-13, Diodes Inc.", "MOSF NPN 400V 1A SOT-223"
R100 R101: "RES, 330 k, 5%, 1 W, 2512"
R102 R103: "RES, 20 k, 5%, 0.25 W, 1206"
R104 R105 R108 R109 R111 R112: "RES, 432 k, 1%, 0.25 W, 1206"
R106 R107 R110: library part WSL2512R0320FEA18, "RES SMD 0.036 OHM 1% 2W 2512"
R113: "RES, 10, 5%, 10 W, TH"
R114 R117: "RES, 10, 5%, 0.25 W, 0603"
R115: "RES, 1.0, 5%, 0.1 W, 0603"
R116: "RES, 221, 1%, 0.1 W, 0603"
R118 R120: "RES, 499k ohm, 1%, 0.25W, 1206"
R119 R121: "RES, 150, 5%, 0.25 W, 1206"
R122: "RES, 5.90 k, 1%, 0.1 W, 0603"
R123: "RES, 10.5 k, 1%, 0.1 W, 0603"
R124: "RES, 13.3 k, 1%, 0.1 W, 0603"
R125 R126: "RES, 3.3Meg ohm, 5%, 0.25W, 1206"
R127: "RES, 49.9 k, 1%, 0.1 W, 0603"
R128: "RES, 475k ohm, 1%, 0.25W, 1206"
R129: "RES, 17.8k ohm, 1%, 0.1W, 0603"
R130: "RES, 511 ohm, 1%, 0.1W, 0603"
R131 R132: "RES, 1.2 ohm, 5%, 0.125W, 0805"
R135: "RES, 12k ohm, 5%, 0.25W, 1206"
RV100: "Varistor 275V RMS 10MM Radial, TH"
TP100: "Test Point, Miniature, Red, TH"
TP102: "Test Point, Miniature, Black, TH"
U100: "Single-Channel High-Speed Low-Side Gate Driver (with 4-A Peak Source and 8-A Peak Sink), DBV0006A"
U101: "8-PIN CONTINUOUS CONDUCTION MODE (CCM) PFC CONTROLLER, D0008A"
U102: "Constant-Voltage, Constant-Current Controller With Primary-Side Regulation, BJT Drive, DBV0006A"

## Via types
v1: diameter 28, hole 10, Top Layer to Bottom Layer, 20 vias

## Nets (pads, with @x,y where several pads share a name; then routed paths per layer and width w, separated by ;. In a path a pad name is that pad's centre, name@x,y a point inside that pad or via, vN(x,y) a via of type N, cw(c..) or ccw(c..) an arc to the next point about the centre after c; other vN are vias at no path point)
15V: C111.1 C112.1 C113.2 C123.1 C124.1 C127.1 D108.2 L103.2 Q102.3 R119.2 R121.2 R128.1 R135.2 TP100.1 U100.1 U101.7 | length 11130
  Top Layer w20: U100.1@6835.87,3417.4 6872.6,3417.4 ; C111.1@6850.59,3262.49 6880,3291.89 6880,3410 6872.6,3417.4 ; D108.2@7568.74,2910 7530,2948.74 7530,3040 7120.94,3449.06 v1(7039.76,3449.06) 7028.82,3460 6915.2,3460 6872.6,3417.4
  Top Layer w50: D108.2@7568.74,2910 7568.74,2781.65 7668.43,2681.97 L103.2@7668.43,2500 7689.21,2479.21 C123.1@7689.21,2140
  Bottom Layer w20: Q102.3@7039.37,3449.06 7108.03,3449.06 C127.1@7130,3427.09 7162.13,3459.21 7162.13,3911.55 7351.5,4100.92 C112.1@7351.5,4160 ; C112.1@7350,4161.5 7350,4250 7375,4275 U101.7@7424.49,4275
  Bottom Layer w25: R121.2@2397.09,850 2487.09,940 C113.2@2490,940 3493.51,940 3676.38,757.13 5776.38,757.13 6346.38,187.13 7803.62,187.13 7892.87,276.38 7892.87,1657.13 TP100.1@7700,1850
  Bottom Layer w50: R119.2@2397.09,745.04 R121.2@2397.09,850 ; TP100.1@7687.09,1862.91 R135.2@7687.09,2060 C124.1@7687.09,2232.91
B+: C100.1 C101.1 C102.1 C104.1 C122.1 D101.1 J100.1 J100.2 Q104.2 Q104.4 R100.2 R101.2 R118.2 R125.1 | length 11641.4
  Top Layer w25: D101.1@6770,1860 6960,1860 7010,1910 R125.1@7010,2352.91 ; R118.2@7500,4036.85 7970,3566.85 7970,870 7950,850 7690,850
  Top Layer w100: C101.1@3740,473.15 C100.1@4670,473.15 C102.1@5600,473.15 5913.15,473.15 6465,1025 ; D101.1@6770,1860 6770,1330 6465,1025 ; J100.2@7670.28,905.28 C104.1@7260,905.28 6584.72,905.28 6465,1025 ; J100.1@7690,775 7690,850 J100.2@7690,925
  Bottom Layer w39.37: Q104.2@7190,2364.17 Q104.4@7190,2135.83 7190,2042.91 C122.1@7232.91,2000
  Bottom Layer w50: C122.1@7232.91,2000 7232.91,1787.09 7260,1760 C104.1@7260,905.28 ; R101.2@7380,726.14 R100.2@7539.69,726.14 7641.14,726.14 J100.1@7690,775 J100.2@7690,925
GND: C100.2 C101.2 C102.2 C104.2 C111.2 C112.2 C113.1 C114.2 C115.2 C116.2 C117.2 C118.2 C119.2 C122.2 C123.2 C124.2 C127.2 D104.1 D106.2 D109.2 HS100.1 HS100.2 HS100.3 J101.1 J101.2 K100.5 Q100.3 Q101.3 Q103.3 R100.1 R101.1 R102.1 R103.1 R106.2 R107.2 R110.2 R123.1 R124.1 R135.1 TP102.1 U100.4 U100.5 U101.1 | length 24798.2
  Top Layer w20: U100.5@6944.13,3380 U100.4@6944.13,3342.6 6944.13,3283.12 C111.2@6964.77,3262.49 6995.08,3232.17 v1(7038.9,3232.17) 7298.41,3232.17 7430,3100.58 v1(7430,3080) ; v1(7338.5,4320) C118.2@7338.5,4380
  Bottom Layer w20: 6859.01,4005 7078.5,4224.5 C115.2@7078.5,4250.79 ; R102.1@6912.91,3837.09 7001.81,3748.19 7001.81,3433.3 7038.9,3396.21 v1(7038.9,3232.17) ; 7052.91,3312.91 C127.2@7130,3312.91 ; D106.2@7056.69,4380 7056.69,4333.27 C114.2@7078.5,4311.46 C115.2@7078.5,4251.46 C115.2@7078.5,4250.79 ; 7070,4390 7078.5,4398.5 R123.1@7078.5,4450 ; C112.2@7288.5,4160 7288.5,4228.5 ; v1(7430,3080) 7740,2770 7740,2381.78 7600,2241.78 C124.2@7600,2240 ; C119.2@7670,4427.09 7378.66,4427.09 7338.5,4386.93 v1(7338.5,4320) 7308.5,4290 7308.5,4248.5 7288.5,4228.5 ; C115.2@7078.5,4250.79 7114.41,4214.88 7168.58,4214.88 7178.7,4225 U101.1@7235.51,4225 7285,4225 7288.5,4228.5
  Bottom Layer w25: D104.1@2100,1284.47 K100.5@2179.04,1284.47 ; K100.5@2190.79,1296.22 2313.78,1296.22 2490,1120 C113.1@2490,1020 3460,1020 3690,790 5790,790 6360,220 7790,220 7860,290 7860,1540 TP102.1@7700,1700 ; HS100.2@6471.34,2501.14 6471.34,2931.34 6487.09,2947.09 R103.1@6580,2947.09
  Bottom Layer w50: R110.2@6396.14,3660 R107.2@6396.14,3830 R106.2@6396.14,4000 6396.14,4240.91 HS100.1@6471.34,4316.1 ; R103.1@6580,2947.09 6580,2964.49 Q101.3@6720.51,3105 ; Q100.3@6740,4005 6859.01,4005 6910,3954.01 R102.1@6910,3837.09 ; R101.1@7380,493.86 R100.1@7539.69,493.86 7641.14,493.86 J101.2@7690,445 7814.37,569.37 7814.37,995.63 7370,1440 7370,1805.56 7347.09,1828.48 C122.2@7347.09,2000 7347.09,2072.09 7447.99,2172.99 D109.2@7470,2172.99 7502.99,2140 C123.2@7590.79,2140 C124.2@7590.79,2220.79 ; 7572.91,2122.13 R135.1@7572.91,2060 7572.91,1827.09 TP102.1@7700,1700
  Bottom Layer w100: C101.2@3740,866.85 C100.2@4670,866.85 C102.2@5600,866.85 5791.57,1058.43 ; Q101.3@6740,3105 6420,3425 ; Q100.3@6740,4005 6565,4005 6420,3860 6420,3425 ; J101.1@7670.28,314.72 C104.2@7260,314.72 6535.28,314.72 5791.57,1058.43 ; J101.1@7690,295 J101.2@7690,445 ; 5791.57,1058.43 6130.16,1397.01 6130.16,3135.16 6420,3425
  other v1: 6050,2020 6100,2020 6150,2020 6200,2020 6050,2060 6100,2060 6150,2060 6050,2100 6100,2100
NetC103_1: C103.1 D100.1 D103.1 L100.1 L104.4 L104.5 L104.6 L105.1 | length 4380.4
  Top Layer w100: D103.1@2240,2982.13 2469.13,2982.13 2550,3063 ; D100.1@2240,4192.13 2550,3882.13 ; C103.1@2984.72,4260 2606.85,3882.13 2550,3882.13 ; L104.4@4441.57,3232.91 L104.5@4244.72,3232.91 L104.6@4047.87,3232.91 3604.96,2790 L105.1@3092.99,2790 2823,2790 2550,3063 ; 2550,3063 2550,3882.13
NetC103_2: C103.2 D100.4 D103.4 HS101.1 HS101.2 HS101.3 R106.1 R107.1 R110.1 R116.2 | length 8260.5
  Top Layer w20: v1(6163.86,3830) 6483.86,4150 6917.05,4150 R116.2@7078.5,4311.46
  Bottom Layer w50: HS101.3@2548.66,4236.97 2851.69,4540 3295.28,4540 C103.2@3575.28,4260 4005.28,3830 v1(6163.86,3830) ; R110.1@6163.86,3660 v1(6163.86,3830) ; R106.1@6163.86,4000 v1(6163.86,3830)
  Bottom Layer w100: D103.4@2240,1997.87 2427.68,1997.87 HS101.2@2548.66,2118.86 2548.66,3131.34 2472.13,3207.87 ; D100.4@2240,3207.87 2472.13,3207.87 ; HS101.3@2550,4235.63 2550,3285.75 2472.13,3207.87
